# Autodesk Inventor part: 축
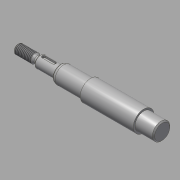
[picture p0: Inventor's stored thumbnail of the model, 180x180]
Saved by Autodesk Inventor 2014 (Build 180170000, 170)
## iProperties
Created: 2015-11
Part Number: 축
Material: 강철, 연강
Document SubType Name: Modeling
Designer: mduedu
Density: 1 g/cm^3
Appearance: Steel
Author: mduedu
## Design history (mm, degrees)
sketch "스케치1"
  geometry: L1 (-86, 0)-(86, 0); L2 (-86, 0)-(-86, 4); L3 (-86, 4)-(-70.732, 4); L4 (-70.732, 4)-(-69, 3); L5 (-69, 3)-(-67, 3); L6 (-67, 3)-(-67, 5); L7 (-67, 5)-(-49, 5); L8 (-49, 5)-(-49, 6.55); L9 (-47.355, 7.5)-(-23, 7.5); L10 (-23, 7.5)-(-23, 9); L11 (0, 0)-(0, 9); L12 (86, 4)-(70.732, 4); L13 (70.732, 4)-(69, 3); L14 (69, 3)-(67, 3); L15 (67, 3)-(67, 5); L16 (67, 5)-(49, 5); L17 (23, 7.5)-(23, 9); L18 (86, 0)-(86, 4); L19 (-23, 9)-(23, 9); L20 (-49, 6.55)-(-47.355, 7.5); L21 (47.355, 7.5)-(23, 7.5); L22 (49, 6.55)-(47.355, 7.5); L23 (49, 5)-(49, 6.55); 1 further point
  constraints: 46 end point, 10 symmetric about line, 6 perpendicular, 5 parallel, 2 midpoint, 1 coincident, 1 horizontal
  dimensions: "d0" = 172 distance of L1.start L1.end (derived); "d1" = 8 diameter of L3 L1; "d2" = 30 deg angle of L4 L5; "d3" = 6 diameter of L5 L1; "d4" = 10 diameter of L7 L1; "d5" = 15 diameter of L9 L1; "d6" = 18 diameter of L19 L1; "d8" = 18 distance of L6.end L7.end; "d9" = 46 distance of L10.end L17.end; "d10" = 2 distance of L4.end L5.end; "d11" = 17 distance from line of L4.end L2; "d16" = 13.1 diameter of L8.end L1; "d17" = 30 deg angle of L20 L9; "d18" = 26 distance between parallel lines of L10 L8
revolve "회전1" sketch "스케치1" stored, may be unused: angle "d12" = 90 deg
chamfer "모따기1" distance "d13" = 1; stored, may be unused: second distance "d14" = 2, angle "d15" = 45 deg
fillet "모깎기1" dims "d19" = 4, "d20" = 0.5
node "작업 평면1"
sketch "스케치2" dims "d23" = 12
  geometry: L1 (-5.5, 1.5)-(3.5, 1.5); L2 (3.5, 1.5)-(3.5, -1.5); L3 (3.5, -1.5)-(-5.5, -1.5); L4 (-5.5, -1.5)-(-5.5, 1.5); L5 (-9, -4)-(-9, 4) reference; 3 further points
  constraints: 8 end point, 2 midpoint, 2 parallel, 2 vertical alignment, 1 horizontal, 1 perpendicular, 4 other
  dimensions: "d21" = 3 distance between parallel lines of L3 L1; "d24" = 2 dimension on L5
extrude "돌출1" cut sketch "스케치2" distance "d25" = 1.8; taper "d26" = 0 deg
feature "스레드1" dims "d27" = 10, "d28" = 0
feature "스레드2" dims "d29" = 10, "d30" = 0
chamfer "모따기2" distance "d31" = 1; stored, may be unused: second distance "d32" = 2, angle "d33" = 45 deg
node "작업 평면2"
sketch "스케치3"
  geometry: C1 r 7.5 at (0, 0) reference; 1 further point
extrude "돌출2" cut sketch "스케치3" stored distance "d36" = 10; taper "d37" = 0 deg
chamfer "모따기3" distance "d38" = 1; stored, may be unused: second distance "d39" = 2, angle "d40" = 45 deg
node "솔리드1"
mirror "대칭1"
node "절단 모서리 투영1"
other parameters: "d35" = 16
